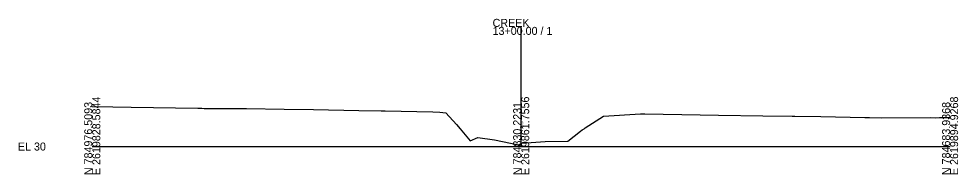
# Model space of a CAD drawing. Extents: x -26 to 303, y -10 to 5021.
# Drawn here: x -25.7 to 302.8, y 2490.3 to 2544.7 of the extents above; entities that cross this region are included whole.
import ezdxf

# ---------------------------------------------------------------- set-up
doc = ezdxf.new("R2010")
doc.units = 0
for name, color, linetype in [('RD_GPK_XS_Cell', 7, 'Continuous'), ('RD_XS_ExGround', 7, 'Continuous'), ('RD_XS_TX_Elev_EX', 7, 'Continuous')]:
    doc.layers.add(name, color=color, linetype=linetype)

msp = doc.modelspace()

# ---------------------------------------------------------------- linework, layer by layer
at = {"layer": 'RD_GPK_XS_Cell'}
for p, q in [((150, 2500), (150, 2541.87)), ((0, 2500), (150, 2500)), ((150, 2500), (300, 2500))]:
    msp.add_line(p, q, dxfattribs=at)
at = {"layer": 'RD_XS_ExGround'}
for p, q in [((0, 2513.96), (7.14, 2513.87)), ((7.14, 2513.87), (13.55, 2513.8)), ((13.55, 2513.8), (36.93, 2513.39)), ((36.93, 2513.39), (38.35, 2513.37)), ((38.35, 2513.37), (39.19, 2513.36)), ((39.19, 2513.36), (54, 2513.3)), ((54, 2513.3), (67.13, 2513.05)), ((67.13, 2513.05), (77.42, 2512.92)), ((77.42, 2512.92), (93.19, 2512.6)), ((93.19, 2512.6), (101.06, 2512.47)), ((101.06, 2512.47), (102.45, 2512.48)), ((102.45, 2512.48), (119.08, 2512.13)), ((119.08, 2512.13), (121.52, 2512.02)), ((121.52, 2512.02), (123.68, 2511.82)), ((123.68, 2511.82), (127.34, 2507.7)), ((172.43, 2506.52), (178.75, 2510.63)), ((178.75, 2510.63), (191.77, 2511.45)), ((191.77, 2511.45), (192.29, 2511.42)), ((192.29, 2511.42), (192.94, 2511.41)), ((192.94, 2511.41), (193.28, 2511.4)), ((193.28, 2511.4), (212.58, 2511.12)), ((212.58, 2511.12), (219.06, 2511.02)), ((219.06, 2511.02), (234.56, 2510.8)), ((234.56, 2510.8), (244.79, 2510.64)), ((244.79, 2510.64), (245.74, 2510.63)), ((245.74, 2510.63), (254.85, 2510.53)), ((254.85, 2510.53), (270.19, 2510.15)), ((270.19, 2510.15), (271.82, 2510.13)), ((271.82, 2510.13), (275.97, 2510.01)), ((275.97, 2510.01), (292.98, 2510.12)), ((292.98, 2510.12), (294.99, 2510.1)), ((294.99, 2510.1), (296.26, 2510.11)), ((296.26, 2510.11), (300, 2510.12)), ((127.34, 2507.7), (128.63, 2506.21)), ((128.63, 2506.21), (132.22, 2501.99)), ((166.29, 2501.92), (170.77, 2505.4)), ((170.77, 2505.4), (171.29, 2505.8)), ((171.29, 2505.8), (172.04, 2506.15)), ((172.04, 2506.15), (172.43, 2506.52)), ((132.22, 2501.99), (134.8, 2503.14)), ((134.8, 2503.14), (140.67, 2502.38)), ((140.67, 2502.38), (149.08, 2500.57)), ((149.08, 2500.57), (150.18, 2501.18)), ((150.18, 2501.18), (158.42, 2501.81)), ((158.42, 2501.81), (166.29, 2501.92))]:
    msp.add_line(p, q, dxfattribs=at)

# ---------------------------------------------------------------- texts
at = {"layer": 'RD_GPK_XS_Cell'}
for s, p in [('CREEK', (140, 2541.87)), ('13+00.00 / 1', (140, 2539.07)), ('EL 30', (-26, 2498.6))]:
    msp.add_text(s, height=2.8, dxfattribs=at).set_placement(p)
for s, p in [('E 2619828.5844', (2.8, 2490)), ('E 2619861.7556', (152.8, 2490)), ('E 2619894.9268', (302.8, 2490)), ('N 784976.5093', (0, 2490)), ('N 784830.2231', (150, 2490)), ('N 784683.9368', (300, 2490))]:
    msp.add_text(s, height=2.8, rotation=90, dxfattribs=at).set_placement(p)
at = {"layer": 'RD_XS_TX_Elev_EX'}
msp.add_text('31.08', height=0.8, rotation=90, dxfattribs=at).set_placement((150.7, 2506.08))

doc.saveas('drawing.dxf')
